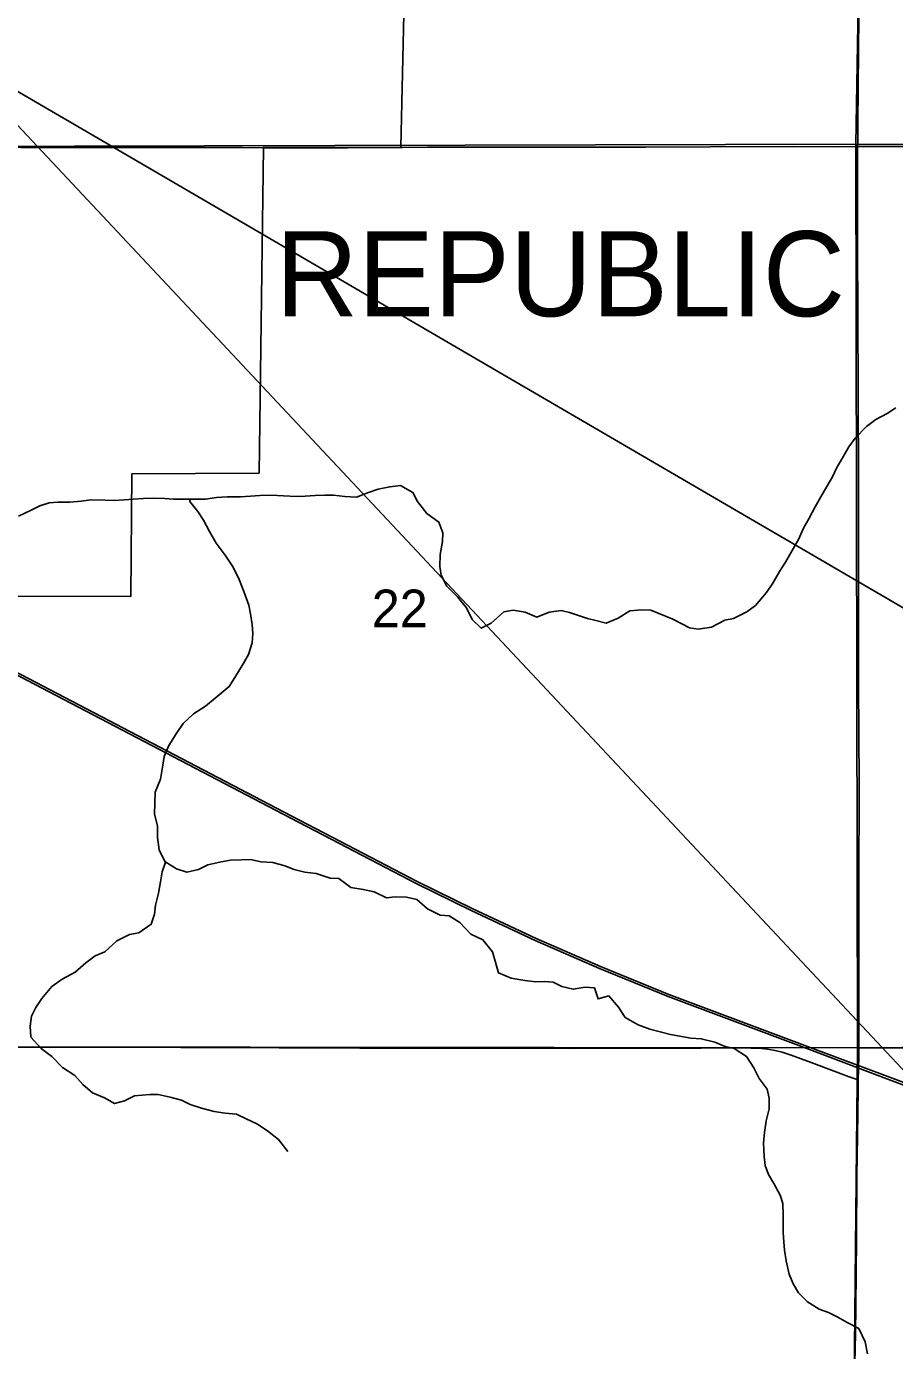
# Model space of a CAD drawing. Extents: x 0 to 34, y 0 to 22.
# Drawn here: x 8.307 to 8.79, y 15.574 to 16.311 of the extents above; entities that cross this region are included whole.
import ezdxf

# ---------------------------------------------------------------- set-up
doc = ezdxf.new("R2010")
doc.units = 0
for name, color, linetype in [('GM_X_Corporation', 7, 'Continuous'), ('GM_X_Corporation_Text', 7, 'Continuous'), ('GM_X_Minor_River', 7, 'Continuous'), ('GM_X_Rail_Line', 7, 'Continuous'), ('GM_X_Section_Text', 7, 'Continuous'), ('GM_X_State_Route', 7, 'Continuous'), ('GM_X_Township_Road', 7, 'Continuous'), ('SH_Text', 7, 'Continuous')]:
    doc.layers.add(name, color=color, linetype=linetype)

msp = doc.modelspace()

# ---------------------------------------------------------------- linework, layer by layer
at = {"layer": 'GM_X_Corporation'}
for points in [[(8.27221, 16.74448), (8.77667, 16.7446), (8.76828, 16.24503), (8.26095, 16.24376)], [(8.9, 16.2445), (8.9, 16.7447), (8.77667, 16.7446), (8.76828, 16.24503)], [(8.01236, 16.2409), (8.01554, 16.49017), (8.26732, 16.49333), (8.39355, 16.49188), (8.52074, 16.49027), (8.51526, 16.24341), (8.43869, 16.24324), (8.43632, 16.062), (8.36545, 16.06157), (8.36494, 15.99333), (8.26284, 15.99353), (8.05412, 15.98999), (8.01372, 15.98918)], [(8.76828, 16.24503), (8.76929, 15.74233), (8.26226, 15.74276), (8.26095, 16.24376)], [(8.9, 15.742), (8.9, 16.2445), (8.76828, 16.24503), (8.76929, 15.74233)], [(8.26226, 15.74276), (8.76929, 15.74233), (8.76425, 15.24174), (8.26181, 15.24197)], [(8.9, 15.24104), (8.9, 15.742), (8.76929, 15.74233), (8.76425, 15.24174)]]:
    msp.add_lwpolyline(points, close=True, dxfattribs=at)
at = {"layer": 'GM_X_Minor_River'}
for points in [[(8.66652, 15.98074), (8.67587, 15.97585), (8.68061, 15.97525), (8.68801, 15.97636), (8.69543, 15.98012), (8.70036, 15.98104), (8.70778, 15.9848), (8.71254, 15.98838), (8.71864, 15.99556), (8.72208, 16.00086), (8.7259, 16.00729), (8.72915, 16.0124), (8.73298, 16.01903), (8.73661, 16.02546), (8.73911, 16.03095), (8.74236, 16.03701), (8.7458, 16.04326), (8.74963, 16.05007), (8.75537, 16.05991), (8.75767, 16.06483), (8.76149, 16.07146), (8.76436, 16.07657), (8.76799, 16.08148), (8.77428, 16.08791), (8.77942, 16.09187), (8.78569, 16.09525), (8.79064, 16.09826)], [(8.30243, 16.03808), (8.30947, 16.04147), (8.31441, 16.04373), (8.31955, 16.04541), (8.32429, 16.04577), (8.33094, 16.04593), (8.33739, 16.04647), (8.34271, 16.04721), (8.35068, 16.04699), (8.35561, 16.04678), (8.3615, 16.04713), (8.36625, 16.04749), (8.37194, 16.04784), (8.37707, 16.04801), (8.3839, 16.04798), (8.38864, 16.04758), (8.40648, 16.04751), (8.41256, 16.04843), (8.41863, 16.04878), (8.42604, 16.04875), (8.43154, 16.04911), (8.43667, 16.04947), (8.44312, 16.04982), (8.44995, 16.04941), (8.45716, 16.049), (8.46191, 16.04917), (8.46761, 16.04952), (8.47292, 16.04969), (8.47767, 16.04967), (8.48412, 16.04907), (8.49057, 16.04867), (8.49722, 16.0513), (8.50254, 16.05317), (8.509, 16.05447), (8.51508, 16.05521), (8.52189, 16.05119), (8.52453, 16.04625), (8.52963, 16.03958), (8.53625, 16.03481), (8.5385, 16.02873), (8.53829, 16.02398), (8.53712, 16.01677), (8.5369, 16.01013), (8.53764, 16.0052), (8.54084, 15.99911), (8.5467, 15.9932), (8.5518, 15.98711), (8.55481, 15.98064), (8.55991, 15.97568), (8.56543, 15.97851), (8.57248, 15.98474), (8.57761, 15.98567), (8.58444, 15.98469), (8.59088, 15.98181), (8.59772, 15.98463), (8.60437, 15.98555), (8.60911, 15.98439), (8.61404, 15.98285), (8.61896, 15.98113), (8.6237, 15.97997), (8.62939, 15.97861), (8.63605, 15.98124), (8.64252, 15.98539), (8.64916, 15.98593), (8.65428, 15.98572), (8.66652, 15.98074)], [(8.39794, 16.04754), (8.39775, 16.04622), (8.40228, 16.04069), (8.40548, 16.03575), (8.40868, 16.02947), (8.41245, 16.023), (8.41736, 16.01634), (8.42189, 16.00968), (8.42527, 16.00283), (8.4279, 15.99617), (8.43053, 15.98857), (8.43146, 15.98363), (8.43238, 15.97775), (8.43293, 15.97281), (8.43253, 15.9675), (8.43041, 15.96105), (8.42754, 15.95594), (8.42277, 15.94837), (8.41971, 15.94326), (8.4119, 15.93684), (8.40657, 15.93231), (8.39991, 15.92816), (8.394, 15.92268), (8.39018, 15.917), (8.38616, 15.91038), (8.38348, 15.90432), (8.3827, 15.89958), (8.38153, 15.8918), (8.37846, 15.88441), (8.37825, 15.87834), (8.37822, 15.87227), (8.37971, 15.86581), (8.37987, 15.85935), (8.38079, 15.85233), (8.3838, 15.84586), (8.39043, 15.84185), (8.39612, 15.83993), (8.40257, 15.84142), (8.40771, 15.84405), (8.41531, 15.84573), (8.42044, 15.84665), (8.42651, 15.84682), (8.43145, 15.84699), (8.43752, 15.84582), (8.44397, 15.84541), (8.4506, 15.84349), (8.45591, 15.84138), (8.46179, 15.84002), (8.46805, 15.83924), (8.47582, 15.83674), (8.48075, 15.83653), (8.48737, 15.83138), (8.4942, 15.8304), (8.50027, 15.82904), (8.50728, 15.82579), (8.51202, 15.82634), (8.51828, 15.82612), (8.52416, 15.82477), (8.53003, 15.81962), (8.53703, 15.81598), (8.54216, 15.81577), (8.54802, 15.81195), (8.55407, 15.80547), (8.56089, 15.8024), (8.56618, 15.79574), (8.56954, 15.78396), (8.57655, 15.78108), (8.58414, 15.77972), (8.59021, 15.77893), (8.59514, 15.7791), (8.59989, 15.7787), (8.60481, 15.77641), (8.61107, 15.77486), (8.61772, 15.77597), (8.62303, 15.77557), (8.6249, 15.76949), (8.63098, 15.77117), (8.63627, 15.76488), (8.64004, 15.75918), (8.64724, 15.75497), (8.65368, 15.75266), (8.66525, 15.74969)], [(8.38433, 15.84554), (8.38245, 15.84017), (8.38148, 15.83467), (8.38031, 15.82823), (8.37877, 15.82159), (8.37818, 15.81666), (8.37625, 15.81097), (8.3694, 15.80626), (8.36427, 15.80533), (8.35724, 15.80175), (8.35057, 15.79571), (8.34505, 15.79346), (8.33991, 15.78949), (8.33401, 15.78439), (8.32678, 15.78044), (8.32107, 15.77629), (8.31535, 15.76967), (8.3121, 15.76475), (8.30961, 15.75982), (8.30902, 15.75432), (8.30937, 15.74825), (8.31504, 15.74196), (8.32109, 15.73738), (8.32695, 15.73128), (8.33376, 15.72689), (8.3383, 15.72193), (8.34359, 15.71717), (8.35022, 15.71448), (8.3559, 15.71123), (8.36141, 15.71273), (8.36693, 15.71555), (8.37547, 15.71627), (8.38022, 15.71625), (8.38686, 15.71471), (8.39311, 15.71316), (8.39804, 15.71067), (8.40429, 15.70875), (8.41131, 15.70682), (8.41738, 15.70585), (8.42383, 15.70525), (8.42913, 15.70276), (8.435, 15.69989), (8.44106, 15.69607), (8.44711, 15.69129), (8.4524, 15.68463)], [(8.66525, 15.74969), (8.67648, 15.74771), (8.68236, 15.7473), (8.68994, 15.74537), (8.69562, 15.74306), (8.70073, 15.7419), (8.70754, 15.7375), (8.71168, 15.73103), (8.7145, 15.72513), (8.71903, 15.71922), (8.72014, 15.71428), (8.72011, 15.7084), (8.71837, 15.70158), (8.71758, 15.69513), (8.71699, 15.68925), (8.71733, 15.68184), (8.71787, 15.67672), (8.71975, 15.67177), (8.72276, 15.66682), (8.72633, 15.66035), (8.72764, 15.6556), (8.72798, 15.64915), (8.72794, 15.63947), (8.72829, 15.63434), (8.72865, 15.62959), (8.72957, 15.62371), (8.73124, 15.6163), (8.73349, 15.61097), (8.7365, 15.60602), (8.74141, 15.60087), (8.74803, 15.59685), (8.75314, 15.59493), (8.75825, 15.59244), (8.76355, 15.58938), (8.76998, 15.58612), (8.77355, 15.5787), (8.77485, 15.57205)]]:
    msp.add_lwpolyline(points, dxfattribs=at)
at = {"layer": 'GM_X_Rail_Line'}
for points in [[(8.2626, 15.96995), (8.45363, 15.87015), (8.4765, 15.85828), (8.49805, 15.84701), (8.52376, 15.83363), (8.55431, 15.81867), (8.58994, 15.80199), (8.62578, 15.78631), (8.66392, 15.77085), (8.74406, 15.74069), (8.78565, 15.72506), (8.84985, 15.70094)], [(8.26317, 15.97105), (8.4542, 15.87125), (8.47707, 15.85938), (8.49863, 15.84811), (8.52432, 15.83474), (8.55485, 15.81979), (8.59046, 15.80312), (8.62626, 15.78746), (8.66437, 15.77201), (8.74449, 15.74185), (8.78609, 15.72623), (8.85029, 15.7021)]]:
    msp.add_lwpolyline(points, dxfattribs=at)
at = {"layer": 'GM_X_State_Route'}
for points in [[(8.51586, 16.24314), (8.53011, 16.24329), (8.58325, 16.24333), (8.60905, 16.24329), (8.65132, 16.24345), (8.68738, 16.24363), (8.73368, 16.24369), (8.75638, 16.24364), (8.76935, 16.24369), (8.79802, 16.2438), (8.82444, 16.24383), (8.84681, 16.24397), (8.8751, 16.24408), (8.9, 16.24406)], [(8.22648, 16.24329), (8.23422, 16.24334), (8.25418, 16.24347), (8.26182, 16.24346), (8.27522, 16.24339), (8.29478, 16.2433), (8.30375, 16.24325), (8.32242, 16.24317), (8.34446, 16.24315), (8.36185, 16.2432), (8.39104, 16.24316), (8.41278, 16.24317), (8.42707, 16.24317), (8.4388, 16.24297)], [(8.4388, 16.24297), (8.46182, 16.24298), (8.4744, 16.24298)], [(8.4744, 16.24298), (8.48546, 16.24299), (8.50755, 16.24309), (8.51537, 16.24313), (8.51586, 16.24314)]]:
    msp.add_lwpolyline(points, dxfattribs=at)
at = {"layer": 'GM_X_Township_Road'}
for points in [[(8.76935, 16.24369), (8.76937, 16.24667), (8.76945, 16.25785), (8.76967, 16.27494), (8.76988, 16.29917), (8.77001, 16.31377), (8.77035, 16.33271), (8.77092, 16.37496), (8.77123, 16.39826), (8.77178, 16.4315), (8.77194, 16.44983), (8.77216, 16.46598), (8.77252, 16.49177), (8.77269, 16.51413), (8.77294, 16.53215), (8.77327, 16.55234), (8.77361, 16.56973), (8.7739, 16.58837), (8.77421, 16.60888), (8.77431, 16.63062), (8.77486, 16.67381), (8.77517, 16.70673), (8.77583, 16.73997), (8.77593, 16.74506)], [(8.76996, 15.74229), (8.76996, 15.74618), (8.77001, 15.77912), (8.77002, 15.85059), (8.77014, 15.87017), (8.77024, 15.8854), (8.77024, 15.89037), (8.77004, 15.91614), (8.76983, 15.94535), (8.76983, 15.97331), (8.76985, 16.01558), (8.7698, 16.06282), (8.7698, 16.07588), (8.76973, 16.08737), (8.76958, 16.11533), (8.76945, 16.14112), (8.76942, 16.15293), (8.7693, 16.18556), (8.76927, 16.20918), (8.76925, 16.23062), (8.76935, 16.24369)], [(8.76996, 15.74229), (8.77504, 15.74232), (8.79399, 15.74244), (8.81606, 15.74255), (8.84495, 15.74268), (8.88876, 15.74296), (8.9, 15.743)], [(8.26281, 15.74232), (8.26792, 15.74235), (8.29402, 15.7425), (8.32479, 15.74261), (8.35368, 15.74257), (8.39285, 15.74242), (8.44754, 15.74222), (8.4923, 15.74209), (8.53799, 15.7421), (8.57094, 15.74208), (8.60886, 15.74196), (8.63775, 15.74206), (8.6822, 15.74214), (8.698, 15.74219)], [(8.698, 15.74219), (8.69899, 15.74219), (8.70987, 15.7421), (8.71577, 15.74187), (8.71917, 15.74154), (8.72345, 15.74081), (8.72737, 15.73986), (8.73241, 15.73825), (8.74349, 15.73416), (8.76465, 15.72618), (8.76969, 15.72436)], [(8.76969, 15.72436), (8.76977, 15.73002), (8.76996, 15.73779), (8.76996, 15.74229)], [(8.76701, 15.49458), (8.76707, 15.50106), (8.76713, 15.51566), (8.76745, 15.55046), (8.76809, 15.58336), (8.76828, 15.59859), (8.76869, 15.63587), (8.76892, 15.67099), (8.76927, 15.69305), (8.76962, 15.71946), (8.76969, 15.72436)]]:
    msp.add_lwpolyline(points, dxfattribs=at)
at = {"layer": 'SH_Text'}
msp.add_lwpolyline([(9.29702, 15.19406), (8.2627, 16.29709), (9.29702, 15.69406)], close=True, dxfattribs=at)

# ---------------------------------------------------------------- texts
at = {"layer": 'GM_X_Corporation_Text'}
msp.add_text('REPUBLIC', height=0.047348, rotation=0.00001, dxfattribs=at).set_placement((8.44562, 16.14928))
at = {"layer": 'GM_X_Section_Text'}
msp.add_text('22', height=0.020928, rotation=0.00001, dxfattribs=at).set_placement((8.49901, 15.97628))

doc.saveas('drawing.dxf')
